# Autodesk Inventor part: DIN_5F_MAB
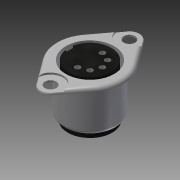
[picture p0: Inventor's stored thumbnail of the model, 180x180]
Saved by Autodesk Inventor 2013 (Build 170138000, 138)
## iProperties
Created: 2013-12
Part Number: DIN_5F_MAB
Material: Acier, non allié
Document SubType Name: Modeling
Designer: leininger-65460
Density: 1 g/cm^3
Author: leininger-65460
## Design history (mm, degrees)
sketch "Esquisse1"
  geometry: L1 (-9.5, 34)-(9.5, 34); L2 (9.5, 34)-(9.5, 6); L3 (9.5, 6)-(-9.5, 6); L4 (-9.5, 6)-(-9.5, 34); L5 (-9.5, 32.5)-(9.5, 32.5); L6 (-8.5, 34)-(-8.5, 6); L7 (-2.54, 32.5)-(-7.621, 25.672); L8 (2.54, 32.5)-(7.621, 25.672); L9 (-9.5, 7.5)-(9.5, 7.5); L10 (-2.54, 7.5)-(-7.621, 14.328); L11 (2.54, 7.5)-(7.621, 14.328); L12 (-7.621, 25.672)-(-2.54, 32.5); L13 (2.54, 32.5)-(7.621, 25.672); L14 (7.621, 14.328)-(2.54, 7.5); L15 (-2.54, 7.5)-(-7.621, 14.328); C1 r 8 at (0, 20) reference; C2 r 1.6 at (0, 31.1) reference; C3 r 1.6 at (0, 8.9) reference; A1 r 2.9 centre (0, 31.1) between (0, 34) and (-2.54, 32.5); A2 r 2.9 centre (0, 8.9) between (-2.54, 7.5) and (2.54, 7.5); A3 r 9.5 centre (0, 20) between (-9.5, 20) and (-7.621, 25.672); A4 r 2.9 centre (0, 8.9) between (-2.54, 7.5) and (2.54, 7.5); A5 r 2.9 centre (0, 31.1) between (2.54, 32.5) and (-2.54, 32.5); A6 r 9.5 centre (0, 20) between (7.621, 14.328) and (7.621, 25.672); A7 r 9.5 centre (0, 20) between (-7.621, 25.672) and (-7.621, 14.328); 1 further point
  constraints: 30 end point, 18 point on circle, 12 tangent, 10 point on line, 7 centre point, 7 coincident, 6 equal length, 4 perpendicular, 2 midpoint, 1 concentric, 1 horizontal, 1 horizontal alignment, 1 vertical alignment
  dimensions: "d0" = 19 distance of L2.end L3.end; "d1" = 28 distance of L1.end L2.end; "d2" = 1 distance between parallel lines of L6 L4; "d3" = 1.5 distance between parallel lines of L1 L5; "d4" = 1.5 distance between parallel lines of L3 L9
extrude "Extrusion1" new body sketch "Esquisse1" distance "d5" = 1; taper "d6" = 0 deg
fillet "Congé1" dims "d7" = 1
sketch "Esquisse2"
  geometry: C1 r 7.45 at (0, 20); A1 r 9.5 centre (0, 20) between (7.621, 14.328) and (7.621, 25.672) reference; 1 further point
  constraints: 1 centre point, 1 coincident
  dimensions: "d8" = 14.9 diameter of C1
extrude "Extrusion2" join sketch "Esquisse2" distance "d9" = 12.1; taper "d10" = 0 deg
fillet "Congé2" dims "d11" = 1
sketch "Esquisse3"
  geometry: C1 r 6.45 at (0, 0) reference; C2 r 6.45 at (0, 0); 1 further point
  constraints: 1 centre point, 1 coincident, 1 concentric
extrude "Extrusion3" join sketch "Esquisse3" distance "d12" = 1.5; taper "d13" = 0 deg
sketch "Esquisse5"
  geometry: C1 r 6.8 at (0, 20); C2 r 6 at (0, 20); A1 r 8.5 centre (0, 20) between (-6.819, 25.075) and (-6.819, 14.925) reference; 1 further point
  constraints: 2 centre point, 2 coincident
  dimensions: "d14" = 13.6 diameter of C1; "d15" = 12 diameter of C2
extrude "Extrusion4" cut sketch "Esquisse5" distance "d16" = 11.1; taper "d17" = 0 deg
sketch "Esquisse6"
  geometry: A1 r 1.9 centre (0, 31.1) between (1.692, 31.963) and (-1.692, 31.963) reference; A2 r 1.9 centre (0, 8.9) between (-1.692, 8.037) and (1.692, 8.037) reference; 3 further points
  constraints: 2 coincident
hole "Perçage1" sketch "Esquisse6" at (0, 31.1), (0, 8.9) diameter "d18" = 3.2; stored, may be unused: countersink angle "d22" = 90 deg, drill point angle "d24" = 118 deg; dims "d19" = 6, "d20" = 4, "d21" = 2, "d23" = 8
sketch "Esquisse7"
  geometry: L1 (0, 0)-(4.243, 4.243); L2 (0, 0)-(6, 0); L3 (4.243, 4.243)-(-4.243, -4.243); L4 (0, 0)-(4.243, -4.243); L5 (0, 0)-(-4.243, 4.243); A1 r 6 centre (0, 0) between (4.243, 4.243) and (-4.243, -4.243) reference; A2 r 3.5 centre (0, 0) between (0, 3.5) and (2.475, 2.475); 4 further points
  constraints: 10 end point, 8 point on circle, 2 collinear, 2 point on line, 1 centre point, 1 coincident, 1 equal length, 1 horizontal, 1 perpendicular
  dimensions: "d28" = 7 diameter of A2; "d29" = 45 deg angle of L2 L1
hole "Perçage2" sketch "Esquisse7" at (0, 3.5), (2.475, 2.475), (3.5, 0), (2.475, -2.475), (0, -3.5) diameter "d30" = 1.5; stored, may be unused: countersink angle "d34" = 90 deg, drill point angle "d36" = 118 deg; dims "d31" = 6, "d32" = 4, "d33" = 2, "d35" = 11
sketch "Esquisse10"
  geometry: L1 (-6, 1.105)-(-5.331, 1.105); L2 (-5.331, 1.105)-(-5.331, -1.105); L3 (-5.331, -1.105)-(-6, -1.105); L4 (-6, -1.105)-(-6, 1.105); C1 r 6 at (0, 0) reference; 2 further points
  constraints: 8 end point, 2 parallel, 1 horizontal, 1 horizontal alignment, 1 midpoint, 1 perpendicular
extrude "Extrusion6" cut sketch "Esquisse10" distance "d39" = 14.75; taper "d40" = 0 deg
sketch "Esquisse11"
  geometry: C1 r 6.45 at (0, 0) reference; C2 r 6.45 at (0, 0); C3 r 6.237 at (0, 0); 1 further point
  constraints: 2 centre point, 2 coincident, 1 concentric
extrude "Extrusion7" cut sketch "Esquisse11" distance "d41" = 13; taper "d42" = 0 deg
sketch "Esquisse12"
  geometry: L1 (6, 1.105)-(6, -1.105) reference; L2 (6, -1.105)-(5.331, -1.105) reference; L3 (5.331, -1.105)-(5.331, 1.105) reference; L4 (5.331, 1.105)-(6, 1.105) reference; L5 (5.331, 1.105)-(6.237, 1.105); L6 (6.237, 1.105)-(6.237, -1.105); L7 (6.237, -1.105)-(5.331, -1.105); L8 (5.331, -1.105)-(5.331, 1.105); 1 further point
  constraints: 8 end point, 2 parallel, 1 horizontal, 1 perpendicular
extrude "Extrusion8" cut sketch "Esquisse12" distance "d43" = 5.25; taper "d44" = 0 deg
sketch "Esquisse13"
  geometry: C1 r 1.6 at (0, 31.1) reference; C2 r 1.6 at (0, 8.9) reference; C3 r 3.451 at (0, 31.1); C4 r 3.55 at (0, 8.9); A1 r 1.9 centre (0, 31.1) between (1.692, 31.963) and (-1.692, 31.963) reference; A2 r 1.9 centre (0, 8.9) between (-1.692, 8.037) and (1.692, 8.037) reference; 1 further point
  constraints: 2 centre point, 2 coincident
extrude "Extrusion9" cut sketch "Esquisse13" distance "d45" = 0.5; taper "d46" = 0 deg
node "Solide1"
node "Référence1"
node "Référence2"
node "Référence3"
